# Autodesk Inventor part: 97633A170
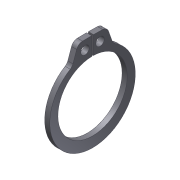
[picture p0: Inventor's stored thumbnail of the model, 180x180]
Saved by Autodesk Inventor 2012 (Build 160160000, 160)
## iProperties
Created: 2012-11
Part Number: 97633A170
Material: Steel
Document SubType Name: Modeling
Designer: Owner
Density: 7.85 g/cm^3
Mass: 0.174689 g
Surface Area: 1.16661 cm^2
Volume: 0.0222534 cm^3
Translation Standard: STEP AP203
FileName: 97633A170.step
PreProcessor: SolidWorks 2007
PostProcessor: Build: 160, Release: 2012 RTM - Date: Tue 03/01/2011
Sent Units: inch
Uncertainty: 1e-05
Author: Owner
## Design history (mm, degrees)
node "97633A1701"
node "NONE"
node "Base1"
